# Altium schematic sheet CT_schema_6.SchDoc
size 267 x 267 mm
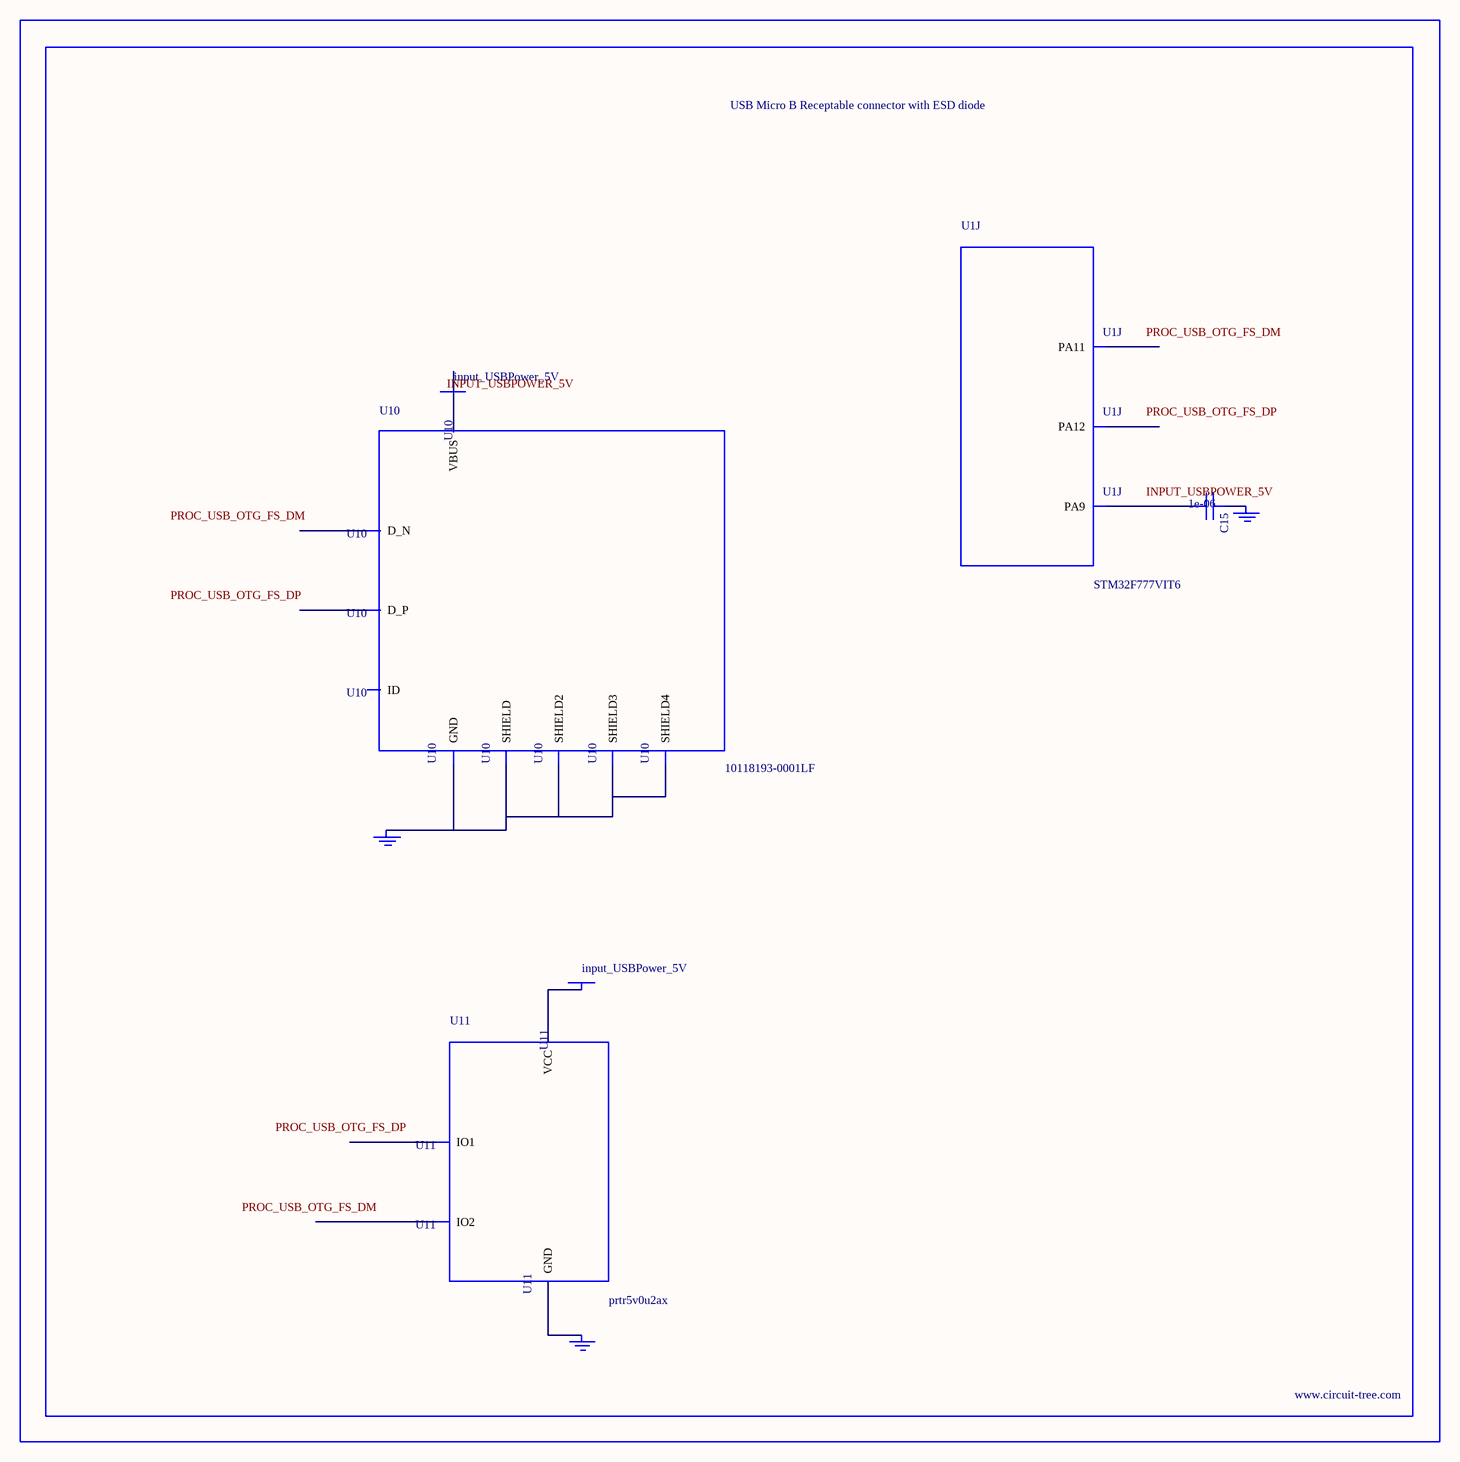
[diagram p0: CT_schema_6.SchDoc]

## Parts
BORDER5  (no value)
C15  1e-06  [C0603]
GND_INSTANCE_5_0  (no value)
GND_INSTANCE_5_1  (no value)
GND_INSTANCE_5_2  (no value)
POWER_INSTANCE_5_0  input_USBPower_5V
POWER_INSTANCE_5_1  input_USBPower_5V
U1  STM32F777VIT6  [LQFP100]  (part J of 11)
U10  10118193-0001LF  [FCI_10118193-0001LF]
U11  prtr5v0u2ax  [SOT143B]

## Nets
NetC15_1: C15.1 GND_INSTANCE_5_1.0(GND)
NetC15_2: C15.2 U1.68(PA9)
NetGND_INSTANCE_5_0_0: GND_INSTANCE_5_0.0(GND) U10.5(GND) U10.6(SHIELD) U10.7(SHIELD2) U10.8(SHIELD3) U10.9(SHIELD4)
NetGND_INSTANCE_5_2_0: GND_INSTANCE_5_2.0(GND) U11.1(GND)
NetPOWER_INSTANCE_5_0_0: POWER_INSTANCE_5_0.0(PWR) U10.1(VBUS)
NetPOWER_INSTANCE_5_1_0: POWER_INSTANCE_5_1.0(PWR) U11.4(VCC)

Not connected (* = marked no-connect by the designer): U1 70(PA11) 71(PA12); U10 2(D_N) 3(D_P) 4(ID); U11 2(IO1) 3(IO2)

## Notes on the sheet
- Labels drawn without touching a wire or pin: INPUT_USBPOWER_5V, PROC_USB_OTG_FS_DM, PROC_USB_OTG_FS_DP

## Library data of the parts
BORDER5 = BORDER_PAGE5
C15 = C0603C105K3RACTU
GND_INSTANCE_5_0-GND_INSTANCE_5_2 = GND
POWER_INSTANCE_5_0 POWER_INSTANCE_5_1 = PWR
